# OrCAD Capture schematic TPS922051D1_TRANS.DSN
size A
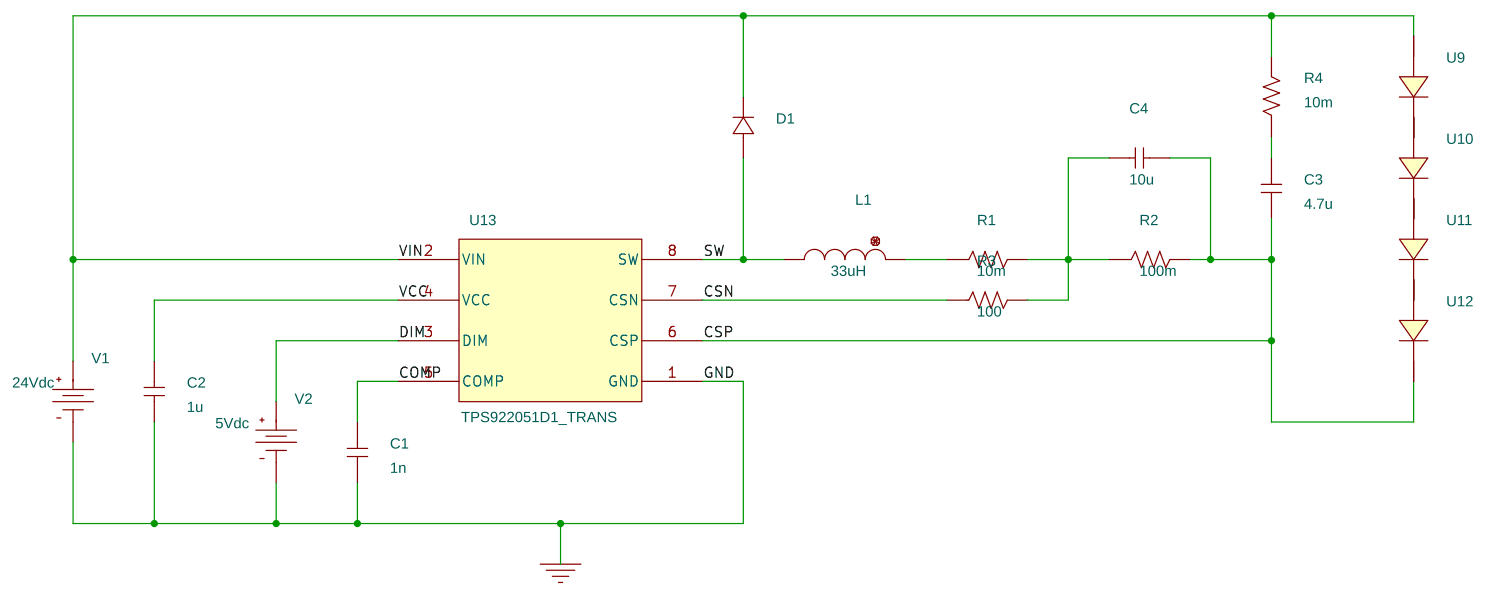
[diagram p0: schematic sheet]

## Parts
C1  1n  [cap196]
C2  1u  [cap196]
C3  4.7u  [cap196]
C4  10u  [cap196]
D1  Dbreak
L1  33uH  [DISC350x175LS200x100034]
R1  10m  [AXRC05]
R2  100m  [AXRC05]
R3  100  [AXRC05]
R4  10m  [AXRC05]
U9  DI_CREE
U10  DI_CREE
U11  DI_CREE
U12  DI_CREE
U13  TPS922051D1_TRANS
V1  VDC
V2  VDC

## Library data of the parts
C1-C4 = C
D1 = Dbreak
L1 = L
R1-R4 = R
U9 = DI_CREE
U10 = DI_CREE_3
U11 = DI_CREE_2
U12 = DI_CREE_1
U13 = TPS922051D1_TRANS
V1 = VDC: DC: 24Vdc
V2 = VDC: DC: 5Vdc

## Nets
VCC: C2.2 U13.4(VCC)
VIN: D1.1(2) R4.2 U9.A U13.2(VIN) V1.0(+)
0: C1.1 C2.1 U13.1(GND) V1.1(-) V2.1(-)
COMP: C1.2 U13.5(COMP)
CSN: R3.1 U13.7(CSN)
CSP: C3.1 C4.1 R2.2 U12.C U13.6(CSP)
DIM: U13.3(DIM) V2.0(+)
SW: D1.0(1) L1.2 U13.8(SW)
N16687762: C3.2 R4.1
N16687804: C4.2 R1.2 R2.1 R3.2
N16687838: U9.C U10.A
N16688136: U10.C U11.A
N16688254: U11.C U12.A
N16689218: L1.1 R1.1
